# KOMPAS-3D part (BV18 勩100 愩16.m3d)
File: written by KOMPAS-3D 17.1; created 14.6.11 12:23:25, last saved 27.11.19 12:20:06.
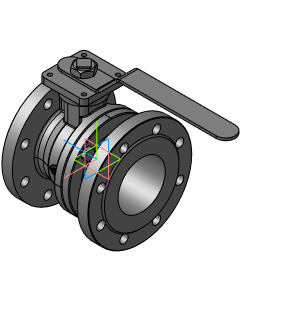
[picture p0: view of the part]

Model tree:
1. Плоскость XY
2. Плоскость ZX
3. Плоскость ZY
4. Ось X
5. Ось Y
6. Ось Z
7. Начало координат
8. Операция без истории:6

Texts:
  Толщина листового тела
  Глубина освобождения сгиба
  Ширина освобождения сгиба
